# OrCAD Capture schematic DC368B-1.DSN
size Custom; title: 100mA Low Noise LDO Regulator; rev: A; note: DEMO BOARD 330
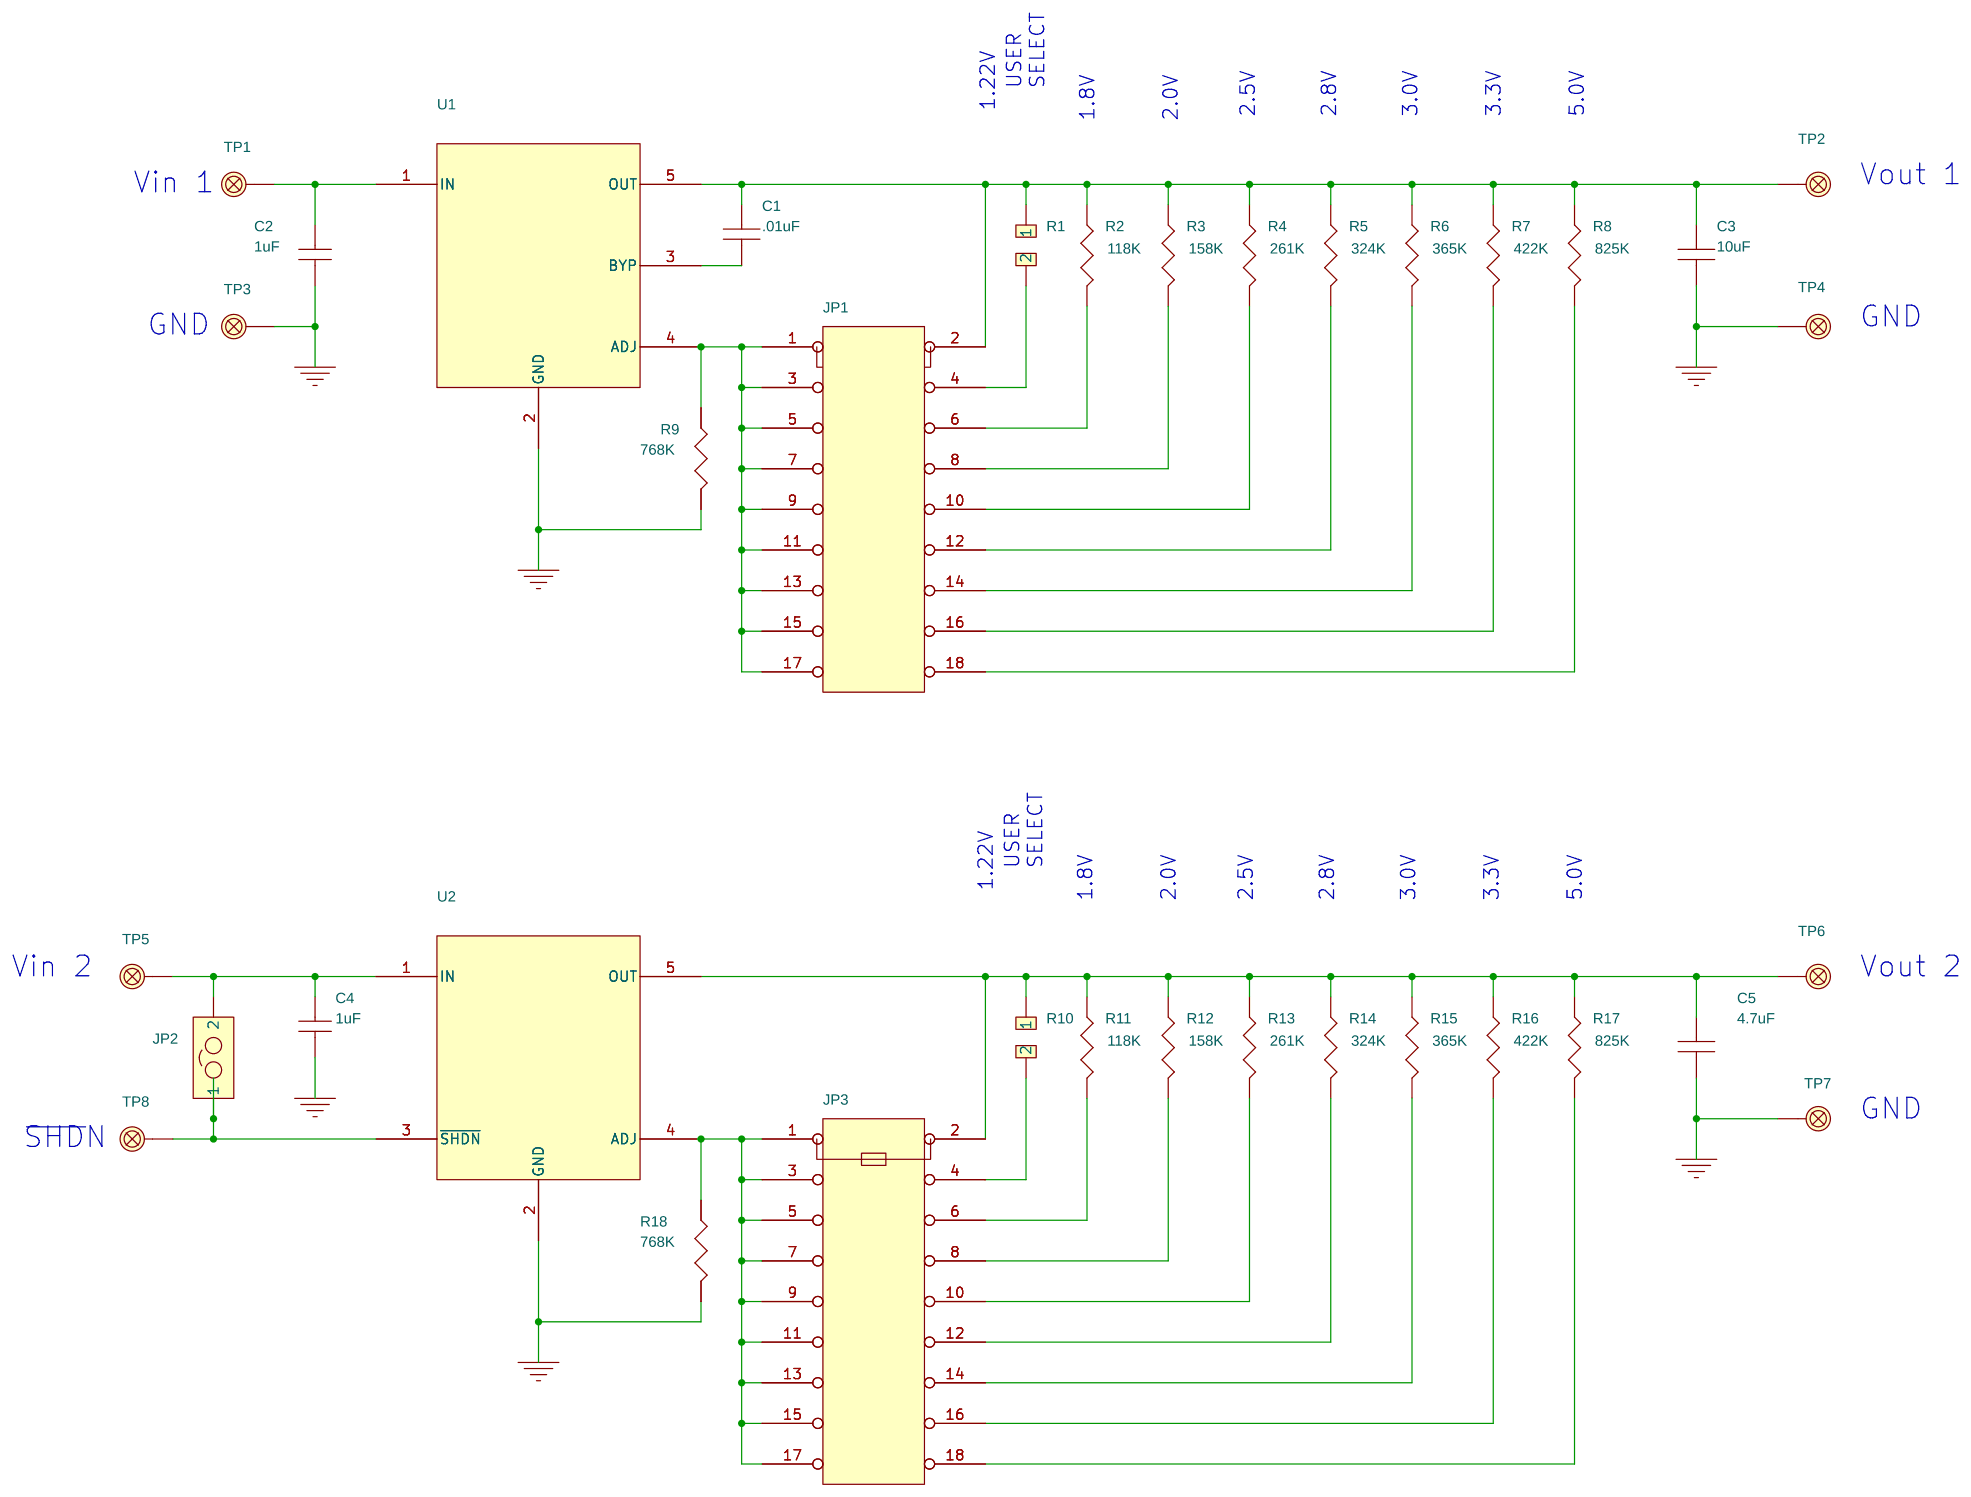
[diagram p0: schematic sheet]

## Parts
C1  .01uF  [0402]
C2  1uF  [0805]
C3  10uF  [1210]
C4  1uF  [0805]
C5  4.7uF  [0805]
JP1  Dbl. Row  2mm Ctr.  [HD2X9-079]
JP2  2pin 2mm Ctr.  [CommCon2802s02g2]
JP3  Dbl. Row  2mm Ctr.  [HD2X9-079]
R1  0 OHM  [0603]
R2  118K  [0402]
R3  158K  [0402]
R4  261K  [0402]
R5  324K  [0402]
R6  365K  [0402]
R7  422K  [0402]
R8  825K  [0402]
R9  768K  [0402]
R10  0 OHM  [0603]
R11  118K  [0402]
R12  158K  [0402]
R13  261K  [0402]
R14  324K  [0402]
R15  365K  [0402]
R16  422K  [0402]
R17  825K  [0402]
R18  768K  [0402]
TP1  Testpoint  [mill-max-2308]
TP2  Testpoint  [mill-max-2308]
TP3  Testpoint  [mill-max-2308]
TP4  Testpoint  [mill-max-2308]
TP5  Testpoint  [mill-max-2308]
TP6  Testpoint  [mill-max-2308]
TP7  Testpoint  [mill-max-2308]
TP8  Testpoint  [mill-max-2308]
U1  LDO REGULATOR  [SOT23-S5]
U2  LDO REGULATOR  [SOT23-S5]
XJP1  2mm Ctrs.
XJP2  2mm Ctrs.

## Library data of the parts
C1 = 0402YC103KAT2A
C2 = GRM40Y5U105Z025AL_1
C3 = LMK325BJ106MN-T
C4 = GRM40Y5U105Z025AL
C5 = JMK212BJ475MD-T
JP1 JP3 = commcon-6351-18p1: 4th Part Field: Samtec INC; 5th Part Field: TMM-109-01-S-D
JP2 = Commcon2802s02g2_2
R1 = CJ06-0R0JM: 6th Part Field: (Optional)
R2 R11 = CR05-1183FM
R3 R12 = CR05-1583FM
R4 R13 = CR05-2613FM
R5 R14 = CR05-3243FM
R6 R15 = CR05-3653FM
R7 R16 = CR05-4223FM
R8 R17 = CR05-8253FM
R9 R18 = CR05-7683FM
R10 = CJ06-0R0JM_1: 6th Part Field: (Optional)
TP1-TP8 = mill-max-2308-2
U1 = LT1761-BYP
U2 = LT1761-SD
XJP1 XJP2 = Samtec_2SN-BK-G_5: 4th Part Field: Interconnect Sys. Inc.; 5th Part Field: CTAIJ1MM

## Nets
gnd: C2.2 C3.2 R9.2 TP3.1 TP4.1 U1.2(GND)
gndB: C4.2 C5.2 R18.2 TP7.1 U2.2(GND)
N09208: C2.1 TP1.1 U1.1(IN)
N09266: C1.1 C3.1 JP1.2 R1.1 R2.1 R3.1 R4.1 R5.1 R6.1 R7.1 R8.1 TP2.1 U1.5(OUT)
N09281: C1.2 U1.3(BYP)
N09420: JP1.4 R1.2
N09427: JP1.6 R2.2
N09434: JP1.8 R3.2
N09441: JP1.10 R4.2
N09448: JP1.12 R5.2
N09455: JP1.14 R6.2
N09462: JP1.16 R7.2
N09469: JP1.18 R8.2
N09476: JP1.1 JP1.3 JP1.5 JP1.7 JP1.9 JP1.11 JP1.13 JP1.15 JP1.17 R9.1 U1.4(ADJ)
N10096: C4.1 JP2.2 TP5.1 U2.1(IN)
N10124: C5.1 JP3.2 R10.1 R11.1 R12.1 R13.1 R14.1 R15.1 R16.1 R17.1 TP6.1 U2.5(OUT)
N10204: JP3.4 R10.2
N10212: JP3.6 R11.2
N10220: JP3.8 R12.2
N10228: JP3.10 R13.2
N10236: JP3.12 R14.2
N10244: JP3.14 R15.2
N10252: JP3.16 R16.2
N10260: JP3.18 R17.2
N10268: JP3.1 JP3.3 JP3.5 JP3.7 JP3.9 JP3.11 JP3.13 JP3.15 JP3.17 R18.1 U2.4(ADJ)
N10992: JP2.1 TP8.1 U2.3(~{SHDN})

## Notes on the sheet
- USER
  SELECT
- 1.22V
- 1.8V
- 2.0V
- 2.5V
- 2.8V
- 3.0V
- 3.3V
- 5.0V
- Vout 1
- Vin 1
- GND
- GND
- USER
  SELECT
- 1.22V
- 1.8V
- 2.0V
- 2.5V
- 2.8V
- 3.0V
- 3.3V
- 5.0V
- Vin 2
- Vout 2
- GND
- SHDN
